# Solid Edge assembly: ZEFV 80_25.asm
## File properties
Title: Zylinder
Author: bmolnar
Template: iso metric assembly.asm
Last saved by: bmolnar
Revision: 11
Application: Solid Edge
Username: bmolnar
Dokumentum tartalom típus: 1
Document Number: ZEFV 80/25
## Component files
Profilrohr.par
Kolbenstange.par
Kit_1.par
Kit_2.par
Mutter.par
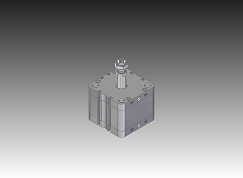
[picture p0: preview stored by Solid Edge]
